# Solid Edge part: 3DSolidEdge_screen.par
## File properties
Author: Administrator
Last saved by: Administrator
Revision: 48
Accuracy: 0.990
Agile_Description: Screen Part
Modeled_By: L. Conard
Part_Number: ITEM-SE-00005
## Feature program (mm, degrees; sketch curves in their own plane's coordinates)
body "unnamed Body 1"
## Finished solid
Body 1: solid body, 10 faces, 24 edges, 16 vertices.
  Faces by surface: plane 6, cylinder 4
  Edges by curve: line 16, circle 8
Bounding box of the edges (mm): 48.000 x 36.000 x 3.000, from (0, 0, 0) to (48, 36, 3).
Cylindrical faces by radius (mm): R1 x4
Planar faces by outward normal: +x 1, +y 1, +z 1, -x 1, -y 1, -z 1
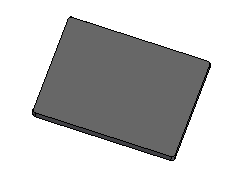
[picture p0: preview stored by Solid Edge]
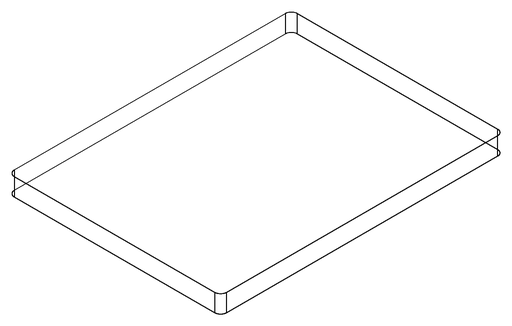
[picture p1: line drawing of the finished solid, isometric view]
